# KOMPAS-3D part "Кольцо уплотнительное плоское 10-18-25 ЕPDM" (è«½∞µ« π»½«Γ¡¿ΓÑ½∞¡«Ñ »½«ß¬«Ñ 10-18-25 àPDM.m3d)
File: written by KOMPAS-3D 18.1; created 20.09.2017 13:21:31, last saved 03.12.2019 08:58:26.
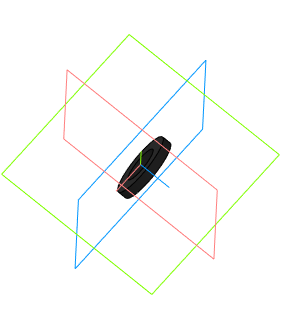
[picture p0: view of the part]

Document properties: Автор: Мирончук; Организация: Мирончук; Полное имя файла: D:\1 ПКИ 3D\РТИ\Кольца уплотнительные  плоские\Кольцо уплотнительное плоское 10-18-25 ЕPDM.m3d

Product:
- Part/product: Кольцо уплотнительное плоское 10-18-25 ЕPDM
    Масса: 0.000562973
    Раздел спецификации: Прочие изделия

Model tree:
1. Эскиз:1
2. Операция выдавливания:1  (labels: 301866972-49-0-0|0; 301866972-49-0-0|1)
     Расстояние 1 = 2.5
